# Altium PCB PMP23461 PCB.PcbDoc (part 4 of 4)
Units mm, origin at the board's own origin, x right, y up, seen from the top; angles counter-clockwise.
Board outline 240.04 x 159.92 mm, 6 copper layers (Layer 1, Layer 2, Layer 3, Layer 4, Layer 5, Layer 6), stack 2.017 mm thick; 241 components, 120 nets, 654 pads, 744 vias.
Unrouted connection lines stored in the file: 3.
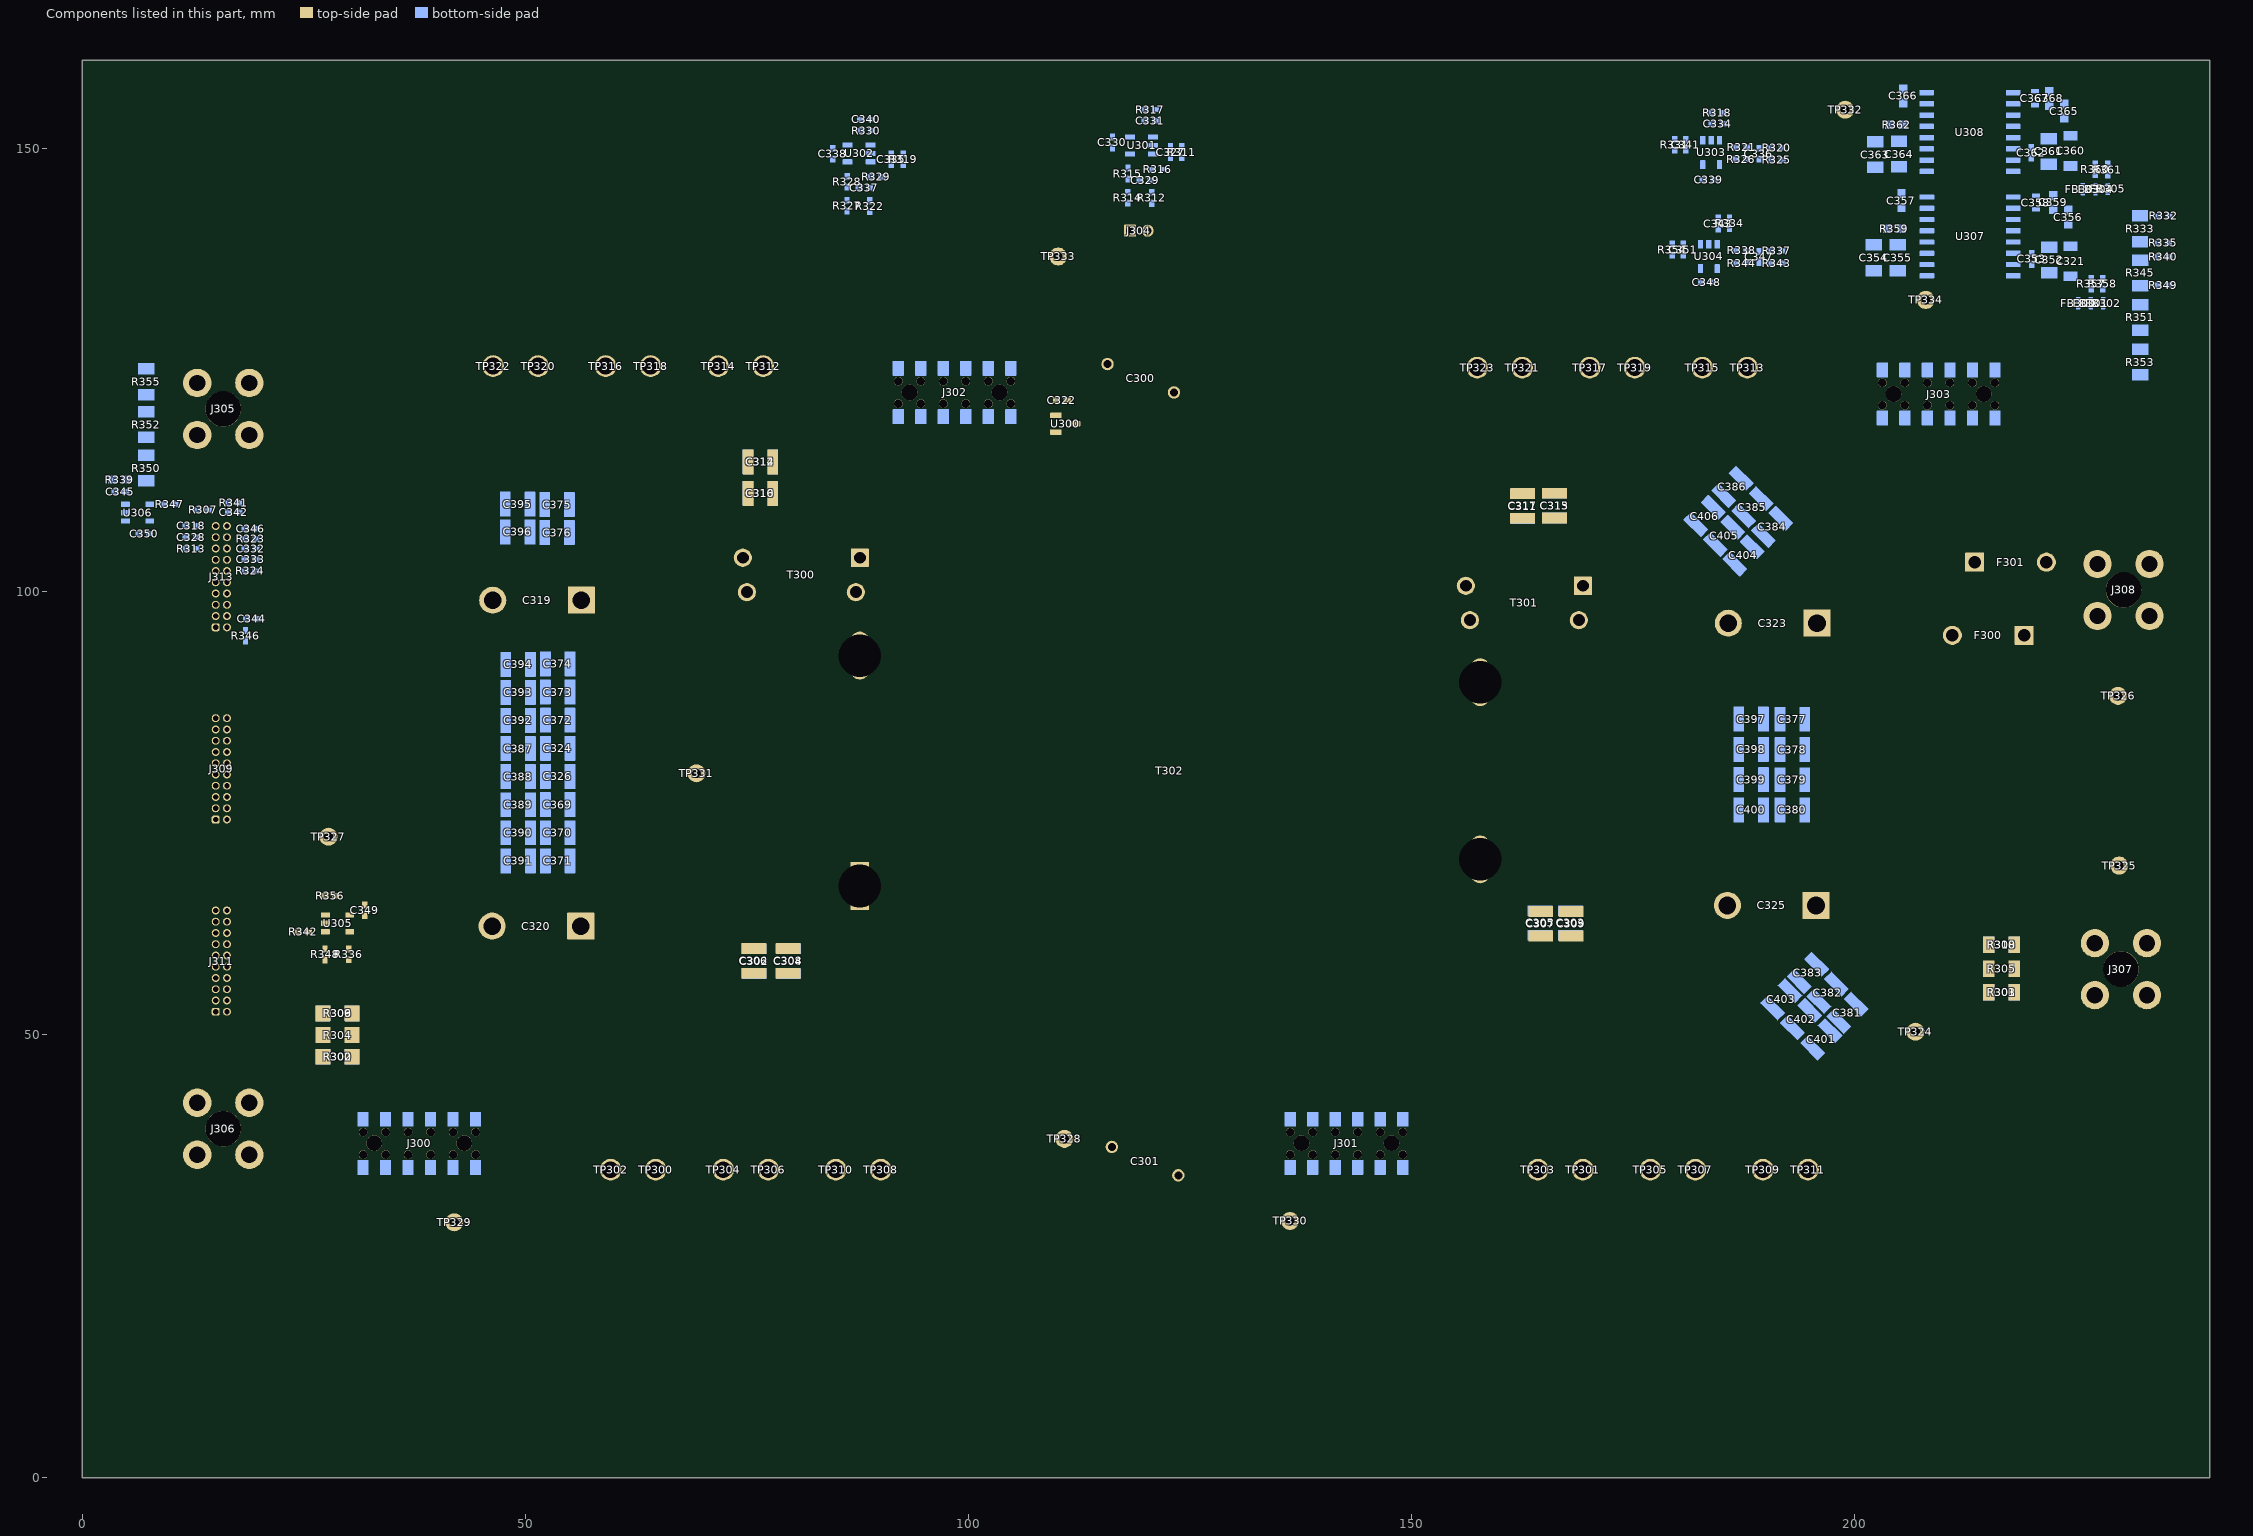
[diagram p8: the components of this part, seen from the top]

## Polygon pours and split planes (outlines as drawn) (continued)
SW_A on Layer 2 "LAYER_2_SW_A_P983" (solid, remove dead copper, pour order 983): 76.148,113.779 76.148,115.139 75.057,116.23 73.697,116.23 65.928,124 65.928,127.022 65.343,127.607 57.825,127.607 56.987,126.768 56.987,120.825 70.497,107.315 75.057,107.315 76.148,108.406
VBATT_F on Layer 2 "LAYER_2_VBATT_F_P963" (solid, remove dead copper, pour order 963): 44 vertices, not listed, extent 155.709,32.103 216.382,128.106
SW_C on Layer 2 "NONET_L-01_P-001" (solid, remove dead copper, pour order 961): 167.688,113.341 167.434,113.596 161.033,113.595 160.805,113.367 160.804,111.82 160.933,111.69 167.41,111.69 167.688,111.968
SW_C_RES on Layer 2 "NONET_L-01_P-001" (solid, remove dead copper, pour order 959): 169.061,108.134 168.379,108.817 161.686,108.817 161.025,108.157 161.025,104.677 161.686,104.017 168.388,104.017 169.061,104.663
5V_PRI on Layer 2 "LAYER_2_5V_PRI_P919" (solid, remove dead copper, pour order 919): 58 vertices, not listed, extent 0,0.61 217.932,159.182
DCLINK on Layer 2 "LAYER_2_DCLINK_P913" (solid, remove dead copper, pour order 913): 39 vertices, not listed, extent 9.93,33.096 92.582,128.013
IPRI_SENSE on Layer 2 "LAYER_2_IPRI_SENSE_P867" (solid, remove dead copper, pour order 867): 12.22,48.87 17.924,48.87 20.182,51.127 20.182,54.633 20.995,55.445 26.989,55.445 28.031,54.404 28.031,34.313 26.862,33.144 12.689,33.144 11.099,34.735 11.099,47.767
SW_C_XFMR on Layer 2 "NONET_L-01_P-001" (solid, remove dead copper, pour order 677): 154.955,87.146 156.216,85.951 165.851,85.951 166.994,87.094 166.994,92.797 165.379,94.412 157.345,94.412 154.955,92.021
SW_D on Layer 2 "NONET_L-01_P-001" (solid, remove dead copper, pour order 673): 169.941,61.719 170.601,61.059 170.601,60.284 170.601,57.503 184.342,43.761 184.342,32.89 183.453,32.001 175.402,32.001 174.538,32.865 174.538,39.265 161.355,52.448 161.355,55.741 161.355,61.099 162.008,61.719
SW_D_RES on Layer 2 "NONET_L-01_P-001" (solid, remove dead copper, pour order 671): 155.056,64.691 156.428,63.319 170.169,63.319 170.703,63.853 170.703,72.463 169.458,73.708 156.199,73.708 155.056,72.51
VBATT on Layer 2 "LAYER_2_VBATT_P665" (solid, remove dead copper, pour order 665): 217.87,107.464 217.058,106.652 217.058,91.716 223.128,85.646 239.003,85.646 239.333,85.976 239.333,106.093 237.962,107.464
BATT_RTN on Layer 2 "LAYER_2_BATT_RTN_P661" (solid, remove dead copper, pour order 661): 217.972,48.409 217.032,49.349 217.032,69.339 218.632,70.939 238.444,70.939 239.384,69.999 239.384,49.425 238.368,48.409
VBATT_F on Layer 2 "LAYER_2_VBATT_F_P659" (solid, remove dead copper, pour order 659): 156.386,128.106 163.491,128.106 164.243,127.354 164.243,123.281 163.057,122.095 157.063,122.095 155.709,123.449 155.709,127.429
SGND on Layer 2 "LAYER_2_SGND_P657" (solid, remove dead copper, pour order 657): 162.549,37.513 163.286,38.249 170.042,38.249 171.083,37.208 171.083,33.144 170.525,32.585 163.286,32.585 162.549,33.322
SW_A_XFMR on Layer 2 "NONET_L-01_P-001" (solid, remove dead copper, pour order 509): 88.051,96.136 85.715,96.136 82.484,99.413 78.341,99.413 77.231,98.323 77.231,90.7 78.12,89.811 83.165,89.811 88.5,89.811 89.194,90.541 89.194,94.993

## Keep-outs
Keep-Out Layer:
  text ".Layer_Name" at 27.726,-9.236 h1.52

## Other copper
Layer 1:
  region net NetC377_1: 189.356,75.558 189.984,74.93 191.388,74.93 191.972,75.489 191.972,85.268 191.058,86.182 189.991,86.182 189.356,85.547
  region net NetC377_1: 183.484,109.809 183.484,110.762 184.101,111.379 184.981,111.379 189.635,106.725 189.635,105.633 189.199,105.196 188.097,105.196
  region net NetC377_1: 194.741,52.654 192.15,55.245 192.15,55.801 192.991,56.642 193.801,56.642 199.033,51.41 199.033,50.557 198.286,49.809 197.586,49.809
  region net NetC324_1: 49.885,92.507 50.545,93.167 52.018,93.167 52.577,92.608 52.577,68.377 51.866,67.666 50.672,67.666 49.885,68.453
  region net NetC324_1: 51.993,110.947 50.824,110.947 49.943,110.065 49.943,106.545 50.672,105.816 52.145,105.816 52.704,106.375 52.704,110.236
  text ".Layer_Name" at 28.092,3.581 h1.52
Layer 3:
  pour cut-out: 152.887,79.407 ccw(c157.314,79.407) 157.314,74.979 ccw(c157.314,79.407) 161.742,79.407 ccw(c157.314,79.407) 157.314,83.835 ccw(c157.314,79.407)
  pour cut-out: 149.318,6 ccw(c153.746,6) 153.746,1.572 ccw(c153.746,6) 158.174,6 ccw(c153.746,6) 153.746,10.428 ccw(c153.746,6)
  pour cut-out: 77.817,6 ccw(c82.245,6) 82.245,1.572 ccw(c82.245,6) 86.673,6 ccw(c82.245,6) 82.245,10.428 ccw(c82.245,6)
  pour cut-out: 71.589,153.918 ccw(c76.017,153.918) 76.017,149.49 ccw(c76.017,153.918) 80.444,153.918 ccw(c76.017,153.918) 76.017,158.346 ccw(c76.017,153.918)
  pour cut-out: 148.887,153.918 ccw(c153.314,153.918) 153.314,149.49 ccw(c153.314,153.918) 157.742,153.918 ccw(c153.314,153.918) 153.314,158.346 ccw(c153.314,153.918)
  pour cut-out: 1.572,140 ccw(c6,140) 6,135.572 ccw(c6,140) 10.428,140 ccw(c6,140) 6,144.428 ccw(c6,140)
  pour cut-out: 9.572,153.918 ccw(c14,153.918) 14,149.49 ccw(c14,153.918) 18.428,153.918 ccw(c14,153.918) 14,158.346 ccw(c14,153.918)
  pour cut-out: 1.572,140 ccw(c6,140) 6,135.572 ccw(c6,140) 10.428,140 ccw(c6,140) 6,144.428 ccw(c6,140)
  pour cut-out: 1.572,20 ccw(c6,20) 6,15.572 ccw(c6,20) 10.428,20 ccw(c6,20) 6,24.428 ccw(c6,20)
  pour cut-out: 9.572,6 ccw(c14,6) 14,1.572 ccw(c14,6) 18.428,6 ccw(c14,6) 14,10.428 ccw(c14,6)
  pour cut-out: 229.613,6 ccw(c234.041,6) 234.041,1.572 ccw(c234.041,6) 238.469,6 ccw(c234.041,6) 234.041,10.428 ccw(c234.041,6)
  pour cut-out: 229.613,153.918 ccw(c234.041,153.918) 234.041,149.49 ccw(c234.041,153.918) 238.469,153.918 ccw(c234.041,153.918) 234.041,158.346 ccw(c234.041,153.918)
  region net NetC377_1: 189.356,75.558 189.984,74.93 191.388,74.93 191.972,75.489 191.972,85.268 191.058,86.182 189.991,86.182 189.356,85.547
  region net NetC377_1: 183.484,109.809 183.484,110.762 184.101,111.379 184.981,111.379 189.635,106.725 189.635,105.633 189.199,105.196 188.097,105.196
  region net NetC377_1: 194.741,52.654 192.15,55.245 192.15,55.801 192.991,56.642 193.801,56.642 199.033,51.41 199.033,50.557 198.286,49.809 197.586,49.809
  region net NetC324_1: 51.993,110.947 50.824,110.947 49.943,110.065 49.943,106.545 50.672,105.816 52.145,105.816 52.704,106.375 52.704,110.236
  region net NetC324_1: 49.885,92.507 50.545,93.167 52.018,93.167 52.577,92.608 52.577,68.377 51.866,67.666 50.672,67.666 49.885,68.453
Layer 4:
  pour cut-out: 152.887,79.407 ccw(c157.314,79.407) 157.314,74.979 ccw(c157.314,79.407) 161.742,79.407 ccw(c157.314,79.407) 157.314,83.835 ccw(c157.314,79.407)
  pour cut-out: 75.589,79.407 ccw(c80.017,79.407) 80.017,74.979 ccw(c80.017,79.407) 84.444,79.407 ccw(c80.017,79.407) 80.017,83.835 ccw(c80.017,79.407)
  pour cut-out: 148.887,153.918 ccw(c153.314,153.918) 153.314,149.49 ccw(c153.314,153.918) 157.742,153.918 ccw(c153.314,153.918) 153.314,158.346 ccw(c153.314,153.918)
  pour cut-out: 71.589,153.918 ccw(c76.017,153.918) 76.017,149.49 ccw(c76.017,153.918) 80.444,153.918 ccw(c76.017,153.918) 76.017,158.346 ccw(c76.017,153.918)
  pour cut-out: 149.318,6 ccw(c153.746,6) 153.746,1.572 ccw(c153.746,6) 158.174,6 ccw(c153.746,6) 153.746,10.428 ccw(c153.746,6)
  pour cut-out: 77.817,6 ccw(c82.245,6) 82.245,1.572 ccw(c82.245,6) 86.673,6 ccw(c82.245,6) 82.245,10.428 ccw(c82.245,6)
  pour cut-out: 9.572,6 ccw(c14,6) 14,1.572 ccw(c14,6) 18.428,6 ccw(c14,6) 14,10.428 ccw(c14,6)
  pour cut-out: 1.572,20 ccw(c6,20) 6,15.572 ccw(c6,20) 10.428,20 ccw(c6,20) 6,24.428 ccw(c6,20)
  pour cut-out: 229.613,6 ccw(c234.041,6) 234.041,1.572 ccw(c234.041,6) 238.469,6 ccw(c234.041,6) 234.041,10.428 ccw(c234.041,6)
  pour cut-out: 229.613,153.918 ccw(c234.041,153.918) 234.041,149.49 ccw(c234.041,153.918) 238.469,153.918 ccw(c234.041,153.918) 234.041,158.346 ccw(c234.041,153.918)
  pour cut-out: 1.572,140 ccw(c6,140) 6,135.572 ccw(c6,140) 10.428,140 ccw(c6,140) 6,144.428 ccw(c6,140)
  pour cut-out: 9.572,153.918 ccw(c14,153.918) 14,149.49 ccw(c14,153.918) 18.428,153.918 ccw(c14,153.918) 14,158.346 ccw(c14,153.918)
  region net 12V_PRI: 15.744,75.677 15.744,70.85 5.969,61.075 5.969,56.185 6.223,55.931 7.569,55.931 7.849,56.21 7.849,60.757 17.272,70.18 17.272,75.692 16.967,75.997 16.064,75.997
  region net NetC377_1: 189.356,75.558 189.984,74.93 191.388,74.93 191.972,75.489 191.972,85.268 191.058,86.182 189.991,86.182 189.356,85.547
  region net NetC377_1: 183.484,109.809 183.484,110.762 184.101,111.379 184.981,111.379 189.635,106.725 189.635,105.633 189.199,105.196 188.097,105.196
  region net NetC377_1: 194.741,52.654 192.15,55.245 192.15,55.801 192.991,56.642 193.801,56.642 199.033,51.41 199.033,50.557 198.286,49.809 197.586,49.809
  region net NetC324_1: 51.993,110.947 50.824,110.947 49.943,110.065 49.943,106.545 50.672,105.816 52.145,105.816 52.704,106.375 52.704,110.236
  region net NetC324_1: 49.885,68.453 49.885,92.507 50.545,93.167 52.018,93.167 52.577,92.608 52.577,68.377 51.866,67.666 50.672,67.666
Layer 2:
  pour cut-out: 152.887,79.407 ccw(c157.314,79.407) 157.314,74.979 ccw(c157.314,79.407) 161.742,79.407 ccw(c157.314,79.407) 157.314,83.835 ccw(c157.314,79.407)
  pour cut-out: 148.887,153.918 ccw(c153.314,153.918) 153.314,149.49 ccw(c153.314,153.918) 157.742,153.918 ccw(c153.314,153.918) 153.314,158.346 ccw(c153.314,153.918)
  pour cut-out: 71.589,153.918 ccw(c76.017,153.918) 76.017,149.49 ccw(c76.017,153.918) 80.444,153.918 ccw(c76.017,153.918) 76.017,158.346 ccw(c76.017,153.918)
  pour cut-out: 149.318,6 ccw(c153.746,6) 153.746,1.572 ccw(c153.746,6) 158.174,6 ccw(c153.746,6) 153.746,10.428 ccw(c153.746,6)
  pour cut-out: 77.817,6 ccw(c82.245,6) 82.245,1.572 ccw(c82.245,6) 86.673,6 ccw(c82.245,6) 82.245,10.428 ccw(c82.245,6)
  pour cut-out: 229.613,153.918 ccw(c234.041,153.918) 234.041,149.49 ccw(c234.041,153.918) 238.469,153.918 ccw(c234.041,153.918) 234.041,158.346 ccw(c234.041,153.918)
  pour cut-out: 229.613,6 ccw(c234.041,6) 234.041,1.572 ccw(c234.041,6) 238.469,6 ccw(c234.041,6) 234.041,10.428 ccw(c234.041,6)
  pour cut-out: 9.572,6 ccw(c14,6) 14,1.572 ccw(c14,6) 18.428,6 ccw(c14,6) 14,10.428 ccw(c14,6)
  pour cut-out: 1.572,20 ccw(c6,20) 6,15.572 ccw(c6,20) 10.428,20 ccw(c6,20) 6,24.428 ccw(c6,20)
  pour cut-out: 1.572,140 ccw(c6,140) 6,135.572 ccw(c6,140) 10.428,140 ccw(c6,140) 6,144.428 ccw(c6,140)
  pour cut-out: 9.572,153.918 ccw(c14,153.918) 14,149.49 ccw(c14,153.918) 18.428,153.918 ccw(c14,153.918) 14,158.346 ccw(c14,153.918)
  region net NetC377_1: 189.356,75.558 189.984,74.93 191.388,74.93 191.972,75.489 191.972,85.268 191.058,86.182 189.991,86.182 189.356,85.547
  region net NetC377_1: 183.484,109.809 183.484,110.762 184.101,111.379 184.981,111.379 189.635,106.725 189.635,105.633 189.199,105.196 188.097,105.196
  region net NetC377_1: 194.741,52.654 192.15,55.245 192.15,55.801 192.991,56.642 193.801,56.642 199.033,51.41 199.033,50.557 198.286,49.809 197.586,49.809
  region net NetC324_1: 51.993,110.947 50.824,110.947 49.943,110.065 49.943,106.545 50.672,105.816 52.145,105.816 52.704,106.375 52.704,110.236
  region net NetC324_1: 49.885,92.507 50.545,93.167 52.018,93.167 52.577,92.608 52.577,68.377 51.866,67.666 50.672,67.666 49.885,68.453
Layer 5:
  pour cut-out: 75.589,79.407 ccw(c80.017,79.407) 80.017,74.979 ccw(c80.017,79.407) 84.444,79.407 ccw(c80.017,79.407) 80.017,83.835 ccw(c80.017,79.407)
  pour cut-out: 152.887,79.407 ccw(c157.314,79.407) 157.314,74.979 ccw(c157.314,79.407) 161.742,79.407 ccw(c157.314,79.407) 157.314,83.835 ccw(c157.314,79.407)
  pour cut-out: 149.318,6 ccw(c153.746,6) 153.746,1.572 ccw(c153.746,6) 158.174,6 ccw(c153.746,6) 153.746,10.428 ccw(c153.746,6)
  pour cut-out: 77.817,6 ccw(c82.245,6) 82.245,1.572 ccw(c82.245,6) 86.673,6 ccw(c82.245,6) 82.245,10.428 ccw(c82.245,6)
  pour cut-out: 148.887,153.918 ccw(c153.314,153.918) 153.314,149.49 ccw(c153.314,153.918) 157.742,153.918 ccw(c153.314,153.918) 153.314,158.346 ccw(c153.314,153.918)
  pour cut-out: 71.589,153.918 ccw(c76.017,153.918) 76.017,149.49 ccw(c76.017,153.918) 80.444,153.918 ccw(c76.017,153.918) 76.017,158.346 ccw(c76.017,153.918)
  pour cut-out: 1.572,20 ccw(c6,20) 6,15.572 ccw(c6,20) 10.428,20 ccw(c6,20) 6,24.428 ccw(c6,20)
  pour cut-out: 1.572,140 ccw(c6,140) 6,135.572 ccw(c6,140) 10.428,140 ccw(c6,140) 6,144.428 ccw(c6,140)
  pour cut-out: 122.016,122.451 ccw(c123.178,122.451) 123.178,121.289 ccw(c123.178,122.451) 124.34,122.451 ccw(c123.178,122.451) 123.178,123.613 ccw(c123.178,122.451)
  pour cut-out: 122.5,34.109 ccw(c123.662,34.109) 123.662,32.947 ccw(c123.662,34.109) 124.824,34.109 ccw(c123.662,34.109) 123.662,35.271 ccw(c123.662,34.109)
  pour cut-out: 208.953,63.183 208.941,63.171 208.941,61.188 210.21,59.893 210.21,27.305 201.244,18.339 166.903,18.339 161.519,23.724 161.519,36.482 163.286,38.249 170.716,38.249 173.279,35.687 173.279,32.512 174.721,31.07 197.409,31.07 198.938,32.599 198.938,49.398 ccw(c198.988,49.145) 198.805,49.327 190.43,57.701 cw(c192.226,59.498) 189.686,59.498 189.686,101.411 ccw(c187.148,101.412) 188.942,103.208 183.98,108.17 ccw(c182.905,107.096) 182.904,108.615 180.248,108.615 cw(c180.248,110.713) 178.917,109.092 182.461,112.636 178.518,116.579 178.518,127.368 179.624,128.473 191.464,128.473 192.481,127.456 192.481,120.803 204.596,108.688 204.596,67.54
  pour cut-out: 9.572,6 ccw(c14,6) 14,1.572 ccw(c14,6) 18.428,6 ccw(c14,6) 14,10.428 ccw(c14,6)
  pour cut-out: 9.572,153.918 ccw(c14,153.918) 14,149.49 ccw(c14,153.918) 18.428,153.918 ccw(c14,153.918) 14,158.346 ccw(c14,153.918)
  pour cut-out: 229.613,153.918 ccw(c234.041,153.918) 234.041,149.49 ccw(c234.041,153.918) 238.469,153.918 ccw(c234.041,153.918) 234.041,158.346 ccw(c234.041,153.918)
  pour cut-out: 229.613,6 ccw(c234.041,6) 234.041,1.572 ccw(c234.041,6) 238.469,6 ccw(c234.041,6) 234.041,10.428 ccw(c234.041,6)
  pour cut-out: 161.922,34.742 ccw(c164.233,34.742) 164.233,32.43 ccw(c164.233,34.742) 166.545,34.742 ccw(c164.233,34.742) 164.233,37.054 ccw(c164.233,34.742)
  pour cut-out: 167.002,34.742 ccw(c169.313,34.742) 169.313,32.43 ccw(c169.313,34.742) 171.625,34.742 ccw(c169.313,34.742) 169.313,37.054 ccw(c169.313,34.742)
  pour cut-out: 185.561,125.244 ccw(c187.873,125.244) 187.873,122.933 ccw(c187.873,125.244) 190.185,125.244 ccw(c187.873,125.244) 187.873,127.556 ccw(c187.873,125.244)
  pour cut-out: 180.481,125.244 ccw(c182.793,125.244) 182.793,122.933 ccw(c182.793,125.244) 185.105,125.244 ccw(c182.793,125.244) 182.793,127.556 ccw(c182.793,125.244)
  pour cut-out: 11.709,32.131 11.735,32.156 27.508,32.156 29.032,33.68 29.032,55.326 27.675,56.683 20.716,56.683 19.456,55.423 19.456,51.486 17.678,49.708 10.414,49.708 10.414,48.946 17.958,48.946 20.091,51.079 20.091,54.83 20.922,55.661 27.092,55.661 28.194,54.559 28.194,34.061 27.978,34.061 26.86,32.944 12.573,32.944 10.897,34.62 10.516,34.62 10.516,34.258 10.091,33.833 11.735,32.189 11.735,32.029
  region net 12V_PRI: 16.18,76.073 28.575,76.073 29.083,75.565 29.083,74.117 28.626,73.66 16.231,73.66 15.848,74.042 15.848,75.742
  region net NetC377_1: 194.741,52.654 192.15,55.245 192.15,55.801 192.991,56.642 193.522,56.642 199.033,51.13 199.033,50.557 198.286,49.809 197.586,49.809
  region net NetC377_1: 183.484,109.809 183.484,110.762 184.101,111.379 184.981,111.379 189.386,106.974 189.386,105.384 189.199,105.196 188.097,105.196
  region net NetC377_1: 189.356,75.558 189.984,74.93 191.388,74.93 191.972,75.489 191.972,85.268 191.058,86.182 189.991,86.182 189.356,85.547
  region net NetC324_1: 51.993,110.947 50.824,110.947 49.943,110.065 49.943,106.545 50.672,105.816 52.145,105.816 52.704,106.375 52.704,110.236
  region net NetC324_1: 50.659,93.243 51.815,93.243 52.577,92.481 52.577,68.377 51.866,67.666 50.672,67.666 49.885,68.453 49.885,92.469
  region net SGND: 200.368,51.395 200.368,32.678 197.587,29.896 173.787,29.896 171.831,31.852 171.831,36.119 170.459,37.49 163.567,37.49 162.462,36.385 162.462,24.609 167.615,19.456 200.914,19.456 209.067,27.61 209.067,51.486 210.795,51.486 211.912,52.603 211.912,61.722 211.252,62.382 207.924,62.382 207.594,62.713 203.783,66.524 203.783,108.078 191.897,119.964 191.897,126.746 190.729,127.914 180.721,127.914 179.807,127 179.807,118.135 185.571,112.446 185.571,112.39 186.242,111.801 190.474,107.569 190.474,88.671 192.988,86.157 192.988,74.752 190.474,72.238 190.474,61.29 190.474,59.487 192.099,57.861 193.877,57.887
  region net PGND: 54.438,112.414 54.177,112.153 54.177,105.791 51.942,103.556 51.942,95.301 51.993,95.301 53.898,93.396 53.898,68.174 51.942,66.269 51.942,38.557 57.911,32.588 64.947,32.588 66.522,34.163 66.521,110.212 76.351,119.99 79.036,119.99 80.314,121.268 80.314,126.289 78.867,127.736 68.096,127.736 67.538,127.178 67.538,125.513
  pour cut-out: 66.706,125.869 66.706,127.57 67.576,128.44 69.277,128.44 79.273,128.44 81.301,126.412 81.301,119.63 80.746,119.075 77.038,119.075 67.176,109.213 67.176,53.059 67.189,53.047 67.189,32.879 65.995,31.685 57.376,31.685 51.293,37.768 50.74,109.903 53.955,113.118
Layer 6:
  rectangle net NetC324_1: 49.91,105.207 52.78,111.251
  pour cut-out: 1.572,140 ccw(c6,140) 6,135.572 ccw(c6,140) 10.428,140 ccw(c6,140) 6,144.428 ccw(c6,140)
  pour cut-out: 1.572,20 ccw(c6,20) 6,15.572 ccw(c6,20) 10.428,20 ccw(c6,20) 6,24.428 ccw(c6,20)
  pour cut-out: 5.385,107.417 5.69,107.112 5.69,105.918 6.045,105.562 7.825,105.562 8.303,106.04 8.303,109.003 8.611,109.31 8.611,113.233 7.823,114.021 4.191,114.021 3.708,113.538 2.819,113.538 2.54,113.259 2.54,110.998 2.972,110.566 3.773,110.566 4.039,110.301 4.039,107.614 4.236,107.417
  pour cut-out: 18.644,97.815 20.294,97.815 20.421,97.688 20.421,96.453 20.234,96.266 18.425,96.266 18.347,96.344 18.347,97.638
  pour cut-out: 85.676,142.41 85.676,147.725 85.319,148.082 84.252,148.082 83.998,148.336 83.998,150.114 94.614,150.114 94.614,147.472 93.827,146.685 90.138,146.685 89.451,145.998 89.451,142.391 89.072,142.011 86.075,142.011
  pour cut-out: 117.094,147.965 117.094,143.307 117.602,142.799 121.144,142.799 121.144,146.512 121.622,146.99 124.943,146.99 125.168,147.215 125.168,150.93 124.968,151.13 116.015,151.13 115.468,150.584 115.468,149.59
  pour cut-out: 183.338,154.5 183.191,154.353 183.191,152.076 182.709,151.594 181.415,151.594 181.415,146.226 181.779,145.862 184.648,145.862 184.887,146.101 184.887,149.902 185.721,150.736 185.721,154.485 185.705,154.5
  pour cut-out: 185.288,134.315 185.445,134.473 185.445,140.259 185.293,140.411 181.774,140.411 180.236,138.873 180.236,134.989 180.909,134.315
  region net NetR352_1: 6.325,122.758 6.325,119.825 6.477,119.672 6.49,119.685 8.077,119.685 8.077,122.658 7.992,122.744
  region net NetR350_1: 6.325,117.932 6.325,114.999 6.477,114.846 6.49,114.859 8.077,114.859 8.077,117.832 7.992,117.918
  region net NetC345_1: 4.496,113.106 4.496,109.83 4.47,109.804 4.547,109.728 5.334,109.728 7.747,112.141 7.747,113.106
  pour cut-out: 18.72,108.179 18.668,108.23 18.668,109.786 12.344,109.786 12.344,108.179 11.289,108.179 10.946,107.836 10.946,104.289 11.172,104.064 14.096,104.064 14.426,103.734 14.426,102.184 14.604,102.006 20.294,102.006 20.294,108.179

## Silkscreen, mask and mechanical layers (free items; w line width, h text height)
Top Overlay:
  lines w0.127: 90.448,49.719 96.15,49.719 ; 90.448,110.719 97.002,110.719 ; 103.631,110.766 110.943,110.766 ; 104.572,49.759 110.033,49.759 ; 130.048,49.759 136.068,49.759 ; 130.429,110.719 135.458,110.719 ; 143.517,110.719 149.448,110.719 ; 144.029,49.719 149.448,49.719
  lines w0.254: 21.02,152.321 71.211,152.321 71.211,157.68 27.878,157.68 21.02,157.68 21.02,152.321 ; 24.222,30.296 24.222,40.474 25.017,41.269 100.239,41.269 101.382,40.126 101.382,30.677 100.087,29.382 25.136,29.382 24.222,30.296 ; 35.053,120.04 36.196,118.897 111.418,118.897 112.213,119.693 112.213,129.87 111.299,130.785 36.348,130.785 35.053,129.489 35.053,120.04 ; 128.844,30.296 128.844,40.474 129.639,41.269 204.861,41.269 206.004,40.126 206.004,30.677 204.709,29.382 129.758,29.382 128.844,30.296 ; 146.102,119.86 146.102,129.309 147.397,130.605 222.348,130.605 223.262,129.69 223.262,119.513 222.467,118.717 147.245,118.717 146.102,119.86 ; 234.99,53.413 239.689,53.413 239.689,104.645 235.066,104.645 234.99,53.413
  text "400 VDC - 450 VDC, 6600 W, 30 A" at 22.367,155.445 h1.52
  text "DCLINK" at 23.662,152.676 h1.52
  text "PGND" at 38.318,152.676 h1.52
  text "+" at 21.706,152.422 h1.52
  text "+" at 32.655,152.422 h1.52
  text "-" at 36.041,152.422 h1.52
  text "-" at 45.455,152.422 h1.52
  text "PMP23461A" at 100.507,150.444 h5.08
  text "DCLINK" at 12.47,127.33 h1.52
  text "HVP042A" at 79.731,124.257 h1.52
  text "HVP042A" at 191.033,124.104 h1.52
  text "+" at 23.291,121.641 h1.52 r180
  text "SGND" at 182.778,116.383 h1.52
  text "VBATT" at 226.862,105.712 h1.52
  text "250 VDC - 450 VDC, 6600 W, 30 A" at 236.87,103.426 h1.52 r270
  text "+" at 230.691,99.597 h1.52 r180
  text "+" at 230.977,95.196 h1.52 r180
  text "-" at 229.669,63.135 h1.52
  text "BATT_RTN" at 225.744,49.764 h1.52
  text "PGND" at 14.01,44.653 h1.52
  text "-" at 23.469,38.862 h1.52
  text "HVP042A" at 46.558,34.823 h1.52
  text "HVP042A" at 151.13,34.239 h1.52
  text ".Layer_Name" at 26.949,-7.645 h1.52
Bottom Overlay:
  text "Clip capacitor leads" at 45.414,56.312 h1.24
  text ".Layer_Name" at 26.949,-7.645 h1.52
Top Paste:
  text ".Layer_Name" at 28.955,-11.405 h1.52
Bottom Paste:
  text ".Layer_Name" at 28.472,-10.541 h1.52
Top Solder:
  text ".Layer_Name" at 27.888,-10.109 h1.52
  text ".Layer_Name" at 28.244,-10.871 h1.52
Bottom Solder:
  text ".Layer_Name" at 27.726,-9.236 h1.52
Drill Guide:
  text ".Layer_Name" at 28.879,-12.573 h1.52
M1 Board Outline:
  drawing of 226 lines, arcs and shapes, not listed
  text ".Layer_Name" at 26.161,-10.871 h1.52
M3 3D STEP Top:
  text ".Layer_Name" at 27.431,-11.633 h1.52
M4 3D STEP Bottom:
  text ".Layer_Name" at 27.914,-9.779 h1.52
M5 Assembly Top:
  circle w0.254: c-28.158,52.679 r1
  lines w0.254: 5.323,0.374 172.963,0.374 ; 5.323,5.538 173.014,5.538 ; 5.323,10.703 5.323,-4.791 107.05,-4.791 173.014,-4.791 173.014,10.703 5.336,10.703 5.336,-4.791 45.354,-4.791 ; 67.934,-4.791 67.934,10.703 ; 89.1,101.292 89.176,101.292 ; 99.133,101.292 99.133,95.323 137.868,95.323 137.843,95.349 137.843,105.204 99.133,105.204 99.133,101.368 ; 100.116,5.538 100.116,10.703 ; 121.452,5.538 121.452,10.703 ; 137.251,-4.956 137.251,0.196 ; 106.296,79.601 106.296,88.567 144.828,88.567 144.828,79.601 106.296,79.601
  lines w1.27: 82.902,107.566 89.176,101.292 99.184,101.292 ; 84.833,97.025 89.1,101.292 ; 145.44,89.23 154.153,97.561 ; 160.96,105.435 154.457,97.866 161.061,94.132
  text "Install 12 AWG solid core" at 101.214,102.13 h1.52
  text "wire in these holes." at 101.214,98.95 h1.52
  text "Thread wire through T2." at 101.214,96.278 h1.52
  text "Install 12 AWG solid core" at 107.185,85.722 h1.52
  text "wire in these holes." at 107.007,83.639 h1.52
  text "Thread wire through T3." at 107.185,81.048 h1.52
  text "COMPONENTS MARKED 'DNP' SHOULD NOT BE POPULATED." at 42.039,15.91 h1.52
  text "ASSEMBLY VARIANT:" at 42.026,12.976 h1.52
  text ".VariantName" at 68.341,12.976 h1.52
  text "PCB VIEWED FROM TOP SIDE" at 6.936,7.346 h1.52
  text "BOARD #:" at 69.839,7.346 h1.52
  text ".PRJ_Number" at 83.695,7.346 h1.52
  text "REV:" at 105.145,7.346 h1.52
  text ".PCB_Rev" at 112.549,7.346 h1.52
  text "SVN REV:" at 126.43,7.346 h1.52
  text ".VersionControl_RevNumber" at 139.283,7.346 h1.52
  text "TID #:" at 69.839,2.181 h1.52
  text ".TID" at 83.695,2.181 h1.52
  text "PLOT NAME =" at 6.936,-3.034 h1.52
  text ".plot_File_Name" at 27.396,-3.034 h1.52
  text "GENERATED    :" at 69.89,-3.034 h1.52
  text ".Print_Date" at 91.975,-3.034 h1.52
  text ".Print_Time" at 110.492,-3.034 h1.52
  text "TEXAS INSTRUMENTS" at 142.61,-3.034 h1.52
M6 Assembly Bottom:
  lines w0.254: 5.31,5.526 173.001,5.526 ; 5.361,0.361 173.001,0.361 ; 41.074,-4.969 41.074,0.183 ; 56.872,5.526 56.872,10.69 ; 78.208,5.526 78.208,10.69 ; 110.39,-4.804 110.39,10.69 ; 132.971,-4.804 172.989,-4.804 172.989,10.69 5.31,10.69 5.31,-4.804 71.274,-4.804 173.001,-4.804 173.001,10.69
  text "of the bottom of the board surface." at 153.873,161.773 h2.54
  text "Trim all leads to within 2 mm" at 81.153,161.519 h2.54
  text "Q6, Q7, Q8, and Q 9:" at 20.512,70.177 h1.52
  text "Bottom of package" at 20.512,67.281 h1.52
  text "should face cold plate." at 20.512,64.386 h1.52
  text "COMPONENTS MARKED 'DNP' SHOULD NOT BE POPULATED." at 167.731,15.923 h1.52
  text ".VariantName" at 141.213,12.976 h1.52
  text "ASSEMBLY VARIANT:" at 167.604,12.976 h1.52
  text ".VersionControl_RevNumber" at 39.042,7.333 h1.52
  text "SVN REV:" at 51.894,7.333 h1.52
  text ".PCB_Rev" at 65.775,7.333 h1.52
  text "REV:" at 73.179,7.333 h1.52
  text ".PRJ_Number" at 94.63,7.333 h1.52
  text "BOARD #:" at 108.485,7.333 h1.52
  text "PCB VIEWED FROM BOTTOM SIDE" at 171.388,7.333 h1.52
  text ".TID" at 94.63,2.169 h1.52
  text "TID #:" at 108.485,2.169 h1.52
  text "TEXAS INSTRUMENTS" at 35.714,-3.047 h1.52
  text ".Print_Time" at 67.833,-3.047 h1.52
  text ".Print_Date" at 86.349,-3.047 h1.52
  text "GENERATED    :" at 108.434,-3.047 h1.52
  text ".plot_File_Name" at 150.929,-3.047 h1.52
  text "PLOT NAME =" at 171.388,-3.047 h1.52
M9 Title Sheet:
  drawing of 57 lines, arcs and shapes, not listed
  text "1" at 36.011,257.942 h2.03
  text "2" at 108.441,257.942 h2.03
  text "3" at 180.688,257.942 h2.03
  text "4" at 253.438,257.942 h2.03
  text "5" at 325.966,257.942 h2.03
  text "6" at 398.667,257.942 h2.03
  text "A" at 2.451,224.769 h2.03
  text "A" at 431.985,224.769 h2.03
  text "B" at 2.451,155.695 h2.03
  text "B" at 431.985,155.695 h2.03
  text "C" at 2.451,86.767 h2.03
  text "C" at 431.985,86.767 h2.03
  text "PROJECT TITLE:" at 343.756,32.756 h1.31
  text ".PRJ_Title" at 345.208,28.886 h2.03
  text "DESIGNED FOR:" at 343.756,24.02 h1.31
  text ".PRJ_Customer" at 345.208,19.957 h2.03
  text "D" at 2.451,17.983 h2.03
  text "D" at 431.985,17.983 h2.03
  text "FILE NAME:" at 343.756,15.313 h1.31
  text ".PCB_File_Name_No_Path" at 345.208,11.83 h2.03
  text "Texas Instruments (TI) and/or its licensors do not warrant the accuracy or completeness of this specification" at 199.529,7.133 h1.31
  text "ENGINEER:" at 343.756,6.897 h1.31
  text "LAYOUT BY:" at 387.435,6.897 h1.31
  text "or any information contained therein. TI and/or its licensors do not warrant that this design will meet" at 198.223,3.864 h1.31
  text ".PRJ_Engineer" at 345.208,2.398 h2.03
  text ".PCB_Layout" at 388.901,2.398 h2.03
  text "the specifications, will be suitable for your application or fit for any particular purpose, or will operate in" at 198.223,0.594 h1.31
  text ".Layer_Name" at 31.285,-0.214 h1.74
  text "ALTIUM DESIGNER VERSION:" at 387.435,-2.1 h1.31
  text "an implementation. TI and/or its licensors do not warrant that the design is production worthy. You should" at 198.223,-2.676 h1.31
  text "completely validate and test your design implementation to confirm the system functionality for your application." at 199.529,-5.946 h1.31
  text ".print_Scale" at 345.208,-5.97 h2.03
  text ".Application_BuildNumber" at 388.901,-5.97 h2.03
  text "1" at 36.011,-11.968 h2.03
  text "2" at 108.441,-11.968 h2.03
  text "3" at 180.688,-11.968 h2.03
  text "4" at 253.438,-11.968 h2.03
  text "5" at 325.966,-11.968 h2.03
  text "6" at 398.667,-11.968 h2.03
M10 Fab Notes:
  drawing of 189 lines, arcs and shapes, not listed
  text "DESIGN INFORMATION" at 378.732,192.051 h1.52
  text "MIN. TRACK WIDTH:" at 362.36,188.695 h1.52
  text "8" at 390.204,188.695 h1.52
  text "MIL" at 394.135,188.695 h1.52
  text "MIN. CLEARANCE:" at 362.36,185.542 h1.52
  text "0.2" at 388.68,185.542 h1.52
  text "mm" at 394.135,185.542 h1.52
  text "MIN. VIA PAD SIZE:" at 362.36,182.389 h1.52
  text "24" at 389.443,182.389 h1.52
  text "MIL" at 394.135,182.389 h1.52
  text "0.05mm (2MIL)" at 380.013,179.09 h1.52
  text "MINIMUM ANNULAR RING" at 353.997,178.881 h1.52
  text "EXTERNAL" at 397.996,178.881 h1.52
  text "PER" at 359.077,176.084 h1.52
  text "IPC-D-275 CLASS 2 LEVEL C" at 364.665,176.084 h1.52
  text "MIL, HOLES" at 402.466,173.532 h1.52
  text "+/-" at 392.498,173.313 h1.52
  text "+/-" at 414.19,173.313 h1.52
  text "REGISTRATION TOLERANCES:" at 353.997,173.286 h1.52
  text "METAL" at 384.472,173.286 h1.52
  text "5" at 399.107,173.287 h1.52
  text "3" at 420.265,173.287 h1.52
  text "MIL" at 423.218,173.286 h1.52
  text "HOLE SIZE TOLERANCE (UNLESS OTHERWISE SPECIFIED):" at 353.997,170.789 h1.52
  text "+/-" at 414.19,170.716 h1.52
  text "3" at 420.265,170.689 h1.52
  text "MIL" at 423.218,170.689 h1.52
  text "MATERIAL:" at 352.098,167.193 h1.52
  text "FR-4 High Tg" at 377.154,163.928 h1.52
  text "X" at 373.485,163.726 h1.52
  text "FR-408" at 362.792,163.611 h1.52
  text "OTHER" at 400.587,163.611 h1.52
  text "89.4 MIL (2.3mm) +/-10%" at 370.922,159.978 h1.52
  text "X" at 367.872,159.916 h1.52
  text "THICKNESS:" at 353.997,159.769 h1.52
  text "OTHER" at 403.559,159.769 h1.52
  text "TOLERANCE:" at 353.997,156.256 h1.52
  text "X" at 375.543,156.256 h1.52
  text "ANSI IPC-6012 TYPE 3 CLASS 2" at 380.064,156.256 h1.52
  text "OTHER +/-" at 380.064,152.593 h1.52
  text "BOW & TWIST:" at 353.997,148.906 h1.52
  text "X" at 375.543,148.906 h1.52
  text "ANSI IPC-6012 TYPE 3 CLASS 2" at 380.064,148.906 h1.52
  text "OTHER +/-" at 380.064,145.18 h1.52
  text "DRILLING:" at 352.098,141.862 h1.52
  text "NC_DRILL FILES" at 396.828,139.19 h1.52
  text "REFERENCE:" at 353.997,139.09 h1.52
  text "X" at 370.691,139.088 h1.52
  text "AS SHOWN" at 375.212,139.09 h1.52
  text "X" at 393.577,139.09 h1.52
  text "OTHER" at 404.397,135.477 h1.52
  text "PTH COPPER THICKNESS:" at 353.989,135.387 h1.52
  text "X" at 382.926,135.387 h1.52
  text "20-30 um" at 386.177,135.387 h1.52
  text "BOARD FINISH:" at 352.098,131.638 h1.52
  text "SILKSCREEN:" at 356.041,128.841 h1.52
  text "X" at 380.369,128.841 h1.52
  text "TOP" at 383.34,128.841 h1.52
  text "X" at 393.323,128.841 h1.52
  text "BOTTOM" at 396.32,128.841 h1.52
  text "SILKSCREEN COLOR:" at 356.041,124.899 h1.52
  text "X" at 380.343,124.899 h1.52
  text "WHITE" at 383.34,124.899 h1.52
  text "OTHER" at 396.32,124.899 h1.52
  text "X" at 383.671,121.256 h1.52
  text "GREEN" at 386.668,121.256 h1.52
  text "OTHER" at 402.365,121.256 h1.52
  text "SOLDER RESIST COLOR:" at 356.041,121.081 h1.52
  text "X" at 383.671,117.338 h1.52
  text "MATTE" at 386.668,117.338 h1.52
  text "SEMI-GLOSS" at 402.353,117.321 h1.52
  text "IMMERSION GOLD (ENIG)" at 379.048,112.949 h1.52
  text "ENEPIG" at 413.021,112.766 h1.52
  text "SURFACE FINISH:" at 352.098,112.74 h1.52
  text "X" at 374.527,112.74 h1.52
  text "IMM. TIN/SILVER OR EQUIV" at 360.469,109.253 h1.52
  text "OTHER" at 396.828,109.153 h1.52
  text "ARRAY/PANEL:" at 352.098,105.206 h1.52
  text "CUT AND TRIM PER M1 BOARD OUTLINE" at 379.048,104.997 h1.52
  text "N.C. ROUTE" at 379.048,101.544 h1.52
  text "X" at 396.523,101.544 h1.52
  text "V. SCORE" at 401.044,101.544 h1.52
  text "CERTIFICATION:" at 352.098,98.264 h1.52
  text "MATERIALS AND WORKMANSHIP FOR ALL PCBS" at 370.513,98.264 h1.52
  text "TO MEET OR EXCEED THE REQUIREMENTS OF:" at 370.513,95.875 h1.52
  text "X" at 361.306,92.607 h1.52
  text "ANSI IPC-A-600F CLASS ->" at 364.557,92.607 h1.52
  text "X" at 406.416,92.607 h1.52
  text "2" at 409.21,92.607 h1.52
  text "1" at 401.209,92.569 h1.52
  text "3" at 418.202,92.569 h1.52
  text "X" at 381.931,88.856 h1.52
  text "RoHS" at 385.182,88.856 h1.52
  text "OTHER" at 401.55,88.856 h1.52
  text "PER ORDER" at 411.635,88.856 h1.52
  text "ALL BOARDS MUST MEET OR EXCEED UL94-V0 REQUIREMENTS." at 352.798,84.949 h1.52
  text "PCB MUST BEAR THE UL94V-0 UL REGISTERED MATERIAL ID NUMBER" at 352.798,82.001 h1.52
  text "ADDITIONAL REQUIREMENTS:" at 352.098,77.698 h1.52
  text "MICROSECTION:" at 353.997,74.977 h1.52
  text "YES" at 377.003,74.977 h1.52
  text "REQUIRED" at 398.885,71.311 h1.52
  text "BARE BOARD ELEC. TEST:" at 353.997,71.238 h1.52
  text "NONE" at 387.163,71.238 h1.52
  text "X" at 395.888,71.238 h1.52
  text "PER ORDER" at 413.922,71.238 h1.52
  text "XX MIL VIAS REQUIRE NON-CONDUCTIVE FILL AND PLANARIZE" at 358.268,66.032 h1.5
  text "XX MIL VIAS REQUIRE CONDUCTIVE FILL AND PLANARIZE" at 358.472,63.391 h1.52
  text "OUTER XX MIL TRACES REQUIRE 50 OHM SINGLE-ENDED IMPEDANCE" at 358.447,59.241 h1.47
  text "LAYER 2 & 3 (INNER LAYERS) XX MIL WIDE, XX MIL SPACE / TRACES REQUIRE 100 OHM DIFFERENTIAL IMPEDANCE" at 358.243,53.254 h1.52
  text ".Layer_Name" at 27.025,-11.989 h1.52
M11 Gerber Information:
  lines w0.254: 5.323,0.374 172.963,0.374 ; 5.323,5.538 173.014,5.538 ; 5.323,10.703 5.323,-4.791 107.05,-4.791 173.014,-4.791 173.014,10.703 5.336,10.703 5.336,-4.791 45.354,-4.791 ; 67.934,-4.791 67.934,10.703 ; 100.116,5.538 100.116,10.703 ; 121.452,5.538 121.452,10.703 ; 137.251,-4.956 137.251,0.196
  text "ALL ARTWORK VIEWED FROM TOP SIDE" at 6.936,7.346 h1.52
  text "BOARD #:" at 69.839,7.346 h1.52
  text ".PRJ_Number" at 83.695,7.346 h1.52
  text "REV:" at 105.145,7.346 h1.52
  text ".PCB_Rev" at 112.549,7.346 h1.52
  text "SVN REV:" at 126.43,7.346 h1.52
  text ".VersionControl_RevNumber" at 139.283,7.346 h1.52
  text "LAYER NAME =" at 6.936,2.194 h1.52
  text "TID #:" at 69.839,2.181 h1.52
  text ".TID" at 83.695,2.181 h1.52
  text "PLOT NAME =" at 6.936,-3.034 h1.52
  text ".plot_File_Name" at 27.396,-3.034 h1.52
  text "GENERATED    :" at 69.89,-3.034 h1.52
  text ".Print_Date" at 91.975,-3.034 h1.52
  text ".Print_Time" at 110.492,-3.034 h1.52
  text "TEXAS INSTRUMENTS" at 142.61,-3.034 h1.52
M12 Stackup:
  drawing of 745 lines, arcs and shapes, not listed
  text "Layer" at 198.911,225.676 h1.52
  text "Name" at 209.323,225.676 h1.52
  text "Material" at 232.939,225.676 h1.52
  text "Thickness" at 254.777,225.676 h1.52
  text "Constant" at 271.282,225.676 h1.52
  text "Board Layer Stack" at 285.757,225.676 h1.52
  text "Board Layer Stack 0" at 314.197,225.676 h1.52
  text "Top Overlay" at 209.323,222.628 h1.52
  text "Top Solder" at 209.323,219.58 h1.52
  text "Solder Resist" at 232.939,219.58 h1.52
  text "0.40mil" at 254.777,219.58 h1.52
  text "3.5" at 271.282,219.58 h1.52
  text "1" at 198.911,216.532 h1.52
  text "Layer 1" at 209.323,216.532 h1.52
  text "2.40mil" at 254.777,216.532 h1.52
  text "Dielectric 1" at 209.323,213.484 h1.52
  text "FR-4" at 232.939,213.484 h1.52
  text "15.00mil" at 254.777,213.484 h1.52
  text "4.2" at 271.282,213.484 h1.52
  text "2" at 198.911,210.436 h1.52
  text "Layer 2" at 209.323,210.436 h1.52
  text "2.40mil" at 254.777,210.436 h1.52
  text "Dielectric 2" at 209.323,207.388 h1.52
  text "FR-4" at 232.939,207.388 h1.52
  text "10.00mil" at 254.777,207.388 h1.52
  text "4.2" at 271.282,207.388 h1.52
  text "3" at 198.911,204.34 h1.52
  text "Layer 3" at 209.323,204.34 h1.52
  text "2.40mil" at 254.777,204.34 h1.52
  text "Dielectric 3" at 209.323,201.292 h1.52
  text "FR-4" at 232.939,201.292 h1.52
  text "15.00mil" at 254.777,201.292 h1.52
  text "4.2" at 271.282,201.292 h1.52
  text "4" at 198.911,198.244 h1.52
  text "Layer 4" at 209.323,198.244 h1.52
  text "2.40mil" at 254.777,198.244 h1.52
  text "Dielectric 4" at 209.323,195.196 h1.52
  text "FR-4" at 232.939,195.196 h1.52
  text "10.00mil" at 254.777,195.196 h1.52
  text "4.2" at 271.282,195.196 h1.52
  text "5" at 198.911,192.148 h1.52
  text "Layer 5" at 209.323,192.148 h1.52
  text "2.40mil" at 254.777,192.148 h1.52
  text "Dielectric 5" at 209.323,189.1 h1.52
  text "FR-4" at 232.939,189.1 h1.52
  text "15.00mil" at 254.777,189.1 h1.52
  text "4.2" at 271.282,189.1 h1.52
  text "6" at 198.911,186.052 h1.52
  text "Layer 6" at 209.323,186.052 h1.52
  text "2.40mil" at 254.777,186.052 h1.52
  text "Bottom Solder" at 209.323,183.004 h1.52
  text "Solder Resist" at 232.939,183.004 h1.52
  text "0.40mil" at 254.777,183.004 h1.52
  text "3.5" at 271.282,183.004 h1.52
  text "Bottom Overlay" at 209.323,179.956 h1.52
  text ".Layer_Name" at 27.726,-9.236 h1.52
M13 Component Bodies Top:
  text ".Layer_Name" at 26.263,-11.481 h1.52
M14 Component Bodies Bottom:
  text ".Layer_Name" at 27.025,-10.947 h1.52
M15 Courtyards Top:
  text ".Layer_Name" at 27.482,-10.922 h1.52
M16 Courtyards Bottom:
  text ".Layer_Name" at 28.066,-11.354 h1.52
Drill Drawing:
  text ".Layer_Name" at 27.761,-10.719 h1.52
M17 Embedded Cavity:
  text ".Layer_Name" at 28.168,-9.652 h1.52
M18 Embedded Assembly:
  text ".Layer_Name" at 27.228,-10.947 h1.52
M19 Embedded Keepout:
  text ".Layer_Name" at 27.396,-8.001 h1.52

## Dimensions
0,0 to 0,159.918 on M2 Board Dimensions
0,0 to 240.039,0 on M2 Board Dimensions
